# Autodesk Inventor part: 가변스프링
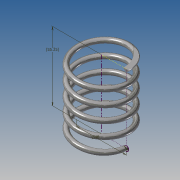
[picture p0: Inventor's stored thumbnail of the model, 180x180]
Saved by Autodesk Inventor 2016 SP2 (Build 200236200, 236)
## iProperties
Created: 2019-03
Part Number: 가변스프링
Material: 스테인레스 스틸
Document SubType Name: Modeling
Designer: EZ
Density: 8 g/cm^3
Appearance: 반연마
Mass: 62.1952 g
Surface Area: 78.8408 cm^2
Volume: 7.7744 cm^3
Author: EZ
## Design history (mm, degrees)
sketch "스케치1"
  geometry: L1 (0, 0)-(20, 0); L2 (20, 0)-(20, 55.25); L3 (20, 55.25)-(0, 55.25); L4 (0, 55.25)-(0, 0); C1 r 2 at (20, 0)
  constraints: 8 end point, 2 parallel, 1 centre point, 1 coincident, 1 horizontal, 1 perpendicular
  dimensions: "d0" = 4 diameter of C1; "d2" = 40 diameter of L2 L4; "d16" = 55.25 distance between parallel lines of L1 L3 (derived)
feature "코일1" sketch "스케치1" pitch "d4" = 10; turns "d6" = 5; dims "d5" = 55.25091 (= d3), "d7" = 0, angle "d8" = 90 deg, angle "d9" = 90 deg, "d10" = 0, "d11" = 0
sketch "스케치2"
  geometry: L1 (-18, 0)-(-22, 0) reference
  constraints: 1 horizontal alignment
extrude "돌출1" cut sketch "스케치2" stored distance "d12" = 10; taper "d13" = 0 deg
node "작업 평면1"
sketch "스케치3"
  geometry: L1 (-2, 0)-(2, 0) reference; 1 further point
  constraints: 2 other
extrude "돌출2" cut sketch "스케치3" stored distance "d14" = 10; taper "d15" = 0 deg
node "솔리드1"
node "절단 모서리 투영1"
node "절단 모서리 투영2"
other parameters: "d3" = 55.25091 (derived)
